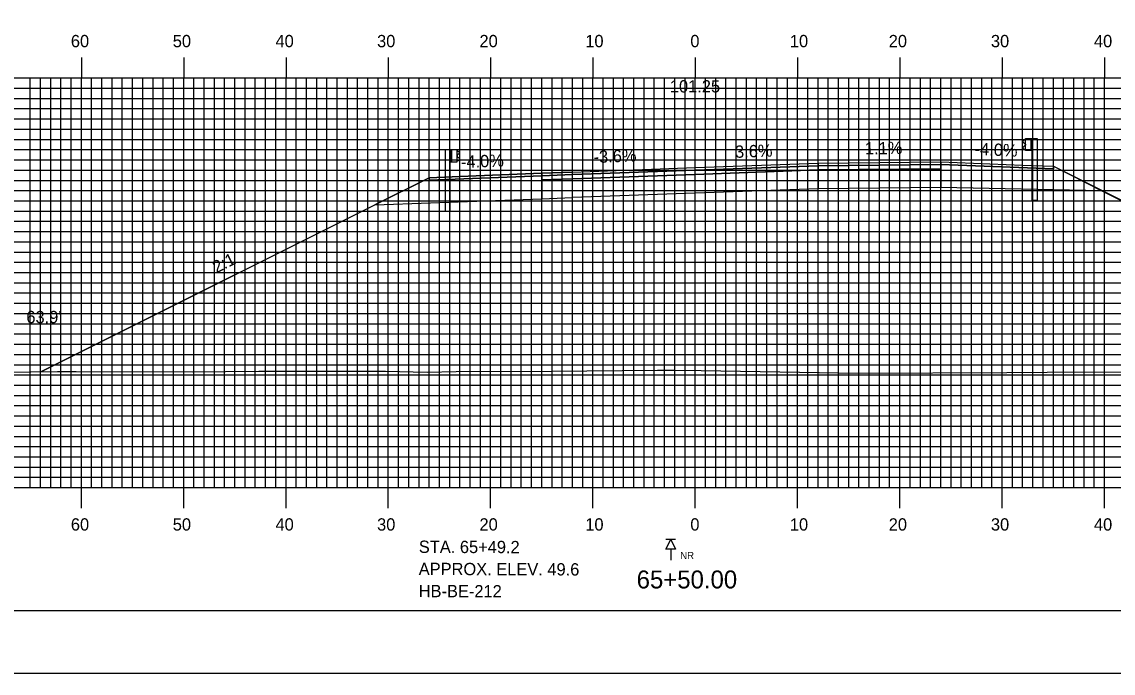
# Model space of a CAD drawing. Extents: x 1759036 to 1759380, y 442591 to 442811.
# Drawn here: x 1759136.3 to 1759243, y 442590.5 to 442654.1 of the extents above; entities that cross this region are included whole.
import ezdxf

# ---------------------------------------------------------------- set-up
doc = ezdxf.new("R2010")
doc.units = 0
for name, color, linetype in [('ANNOTATION', 7, 'Continuous'), ('BORDER', 7, 'Continuous'), ('BORING - NO REFUSAL', 7, 'Continuous'), ('D_Guardrail_Beam_Lt', 7, 'Continuous'), ('D_Guardrail_Beam_Rt', 7, 'Continuous'), ('D_Roadway_Centerline', 7, 'Continuous'), ('D_Roadway_Centerline_Text', 7, 'Continuous'), ('D_Roadway_Edge_Shoulder', 7, 'Continuous'), ('D_Roadway_Edge_TW', 7, 'Continuous'), ('D_Roadway_Pavement', 7, 'Continuous'), ('D_Roadway_SlopeLines', 7, 'Continuous'), ('D_Roadway_SubGrade', 7, 'Continuous'), ('D_Text_Standard', 7, 'Continuous'), ('H_V ANNOTATION', 7, 'Continuous'), ('MAJOR', 7, 'Continuous'), ('MINOR', 7, 'Continuous'), ('PLOT BOUNDARY', 7, 'Continuous'), ('S_Roadway_Centerline', 7, 'Continuous')]:
    doc.layers.add(name, color=color, linetype=linetype)

msp = doc.modelspace()

# ---------------------------------------------------------------- linework, layer by layer
at = {"layer": 'BORDER'}
msp.add_lwpolyline([(1759052.56, 442596.67), (1759372.56, 442596.67), (1759372.56, 442806.67), (1759052.56, 442806.67)], close=True, dxfattribs=at)
at = {"layer": 'BORING - NO REFUSAL'}
for p, q in [((1759200.24, 442603.61), (1759199.28, 442603.61)), ((1759199.76, 442602.65), (1759199.76, 442601.59))]:
    msp.add_line(p, q, dxfattribs=at)
msp.add_lwpolyline([(1759199.76, 442603.61), (1759200.24, 442602.65), (1759199.28, 442602.65)], close=True, dxfattribs=at)
at = {"layer": 'D_Guardrail_Beam_Lt'}
for p, q in [((1759177.72, 442641.64), (1759177.72, 442635.64)), ((1759178.19, 442641.64), (1759177.72, 442641.64)), ((1759178.88, 442641.64), (1759178.19, 442641.64)), ((1759178.19, 442641.64), (1759178.19, 442640.47)), ((1759178.25, 442641.64), (1759178.25, 442640.47)), ((1759178.35, 442641.64), (1759178.35, 442640.47)), ((1759178.88, 442640.47), (1759178.88, 442641.64)), ((1759178.88, 442641.55), (1759178.95, 442641.54)), ((1759178.88, 442641.09), (1759178.88, 442641.02)), ((1759179.11, 442641.29), (1759178.91, 442641.15)), ((1759178.91, 442640.96), (1759179.11, 442640.82)), ((1759178.97, 442641.53), (1759179.11, 442641.43)), ((1759178.19, 442640.47), (1759178.88, 442640.47)), ((1759178.21, 442635.64), (1759178.21, 442640.47)), ((1759178.95, 442640.57), (1759178.88, 442640.55)), ((1759179.11, 442640.68), (1759178.97, 442640.58)), ((1759178.21, 442635.64), (1759177.72, 442635.64))]:
    msp.add_line(p, q, dxfattribs=at)
for centre, major_axis, start_param, end_param in [((1759178.96, 442641.09), (-0.0789, 0), 5.323254, 6.283185), ((1759178.96, 442641.02), (-0.0789, 0), 6.283185, 7.243116), ((1759178.94, 442641.5), (0.0417, 0), 0.959931, 1.376053), ((1759179.06, 442641.36), (0.0877, 0), 5.323254, 7.243116), ((1759179.06, 442640.75), (0.0877, 0), 5.323254, 7.243116), ((1759178.94, 442640.61), (0.0417, 0), 4.907132, 5.323254)]:
    msp.add_ellipse(centre, major_axis=major_axis, ratio=0.995501, start_param=start_param, end_param=end_param, dxfattribs=at)
at = {"layer": 'D_Guardrail_Beam_Rt'}
for p, q in [((1759234.34, 442642.64), (1759234.2, 442642.54)), ((1759234.2, 442642.4), (1759234.39, 442642.26)), ((1759234.39, 442642.06), (1759234.2, 442641.92)), ((1759234.43, 442642.66), (1759234.36, 442642.65)), ((1759234.43, 442642.74), (1759235.12, 442642.74)), ((1759234.43, 442641.58), (1759234.43, 442642.74)), ((1759234.43, 442642.19), (1759234.43, 442642.12)), ((1759234.95, 442642.74), (1759234.95, 442641.58)), ((1759235.06, 442642.74), (1759235.06, 442641.58)), ((1759235.12, 442642.74), (1759235.59, 442642.74)), ((1759235.12, 442642.74), (1759235.12, 442641.58)), ((1759235.59, 442642.74), (1759235.59, 442636.74)), ((1759234.2, 442641.78), (1759234.34, 442641.68)), ((1759234.36, 442641.67), (1759234.43, 442641.66)), ((1759235.12, 442641.58), (1759234.43, 442641.58)), ((1759235.1, 442636.74), (1759235.1, 442641.58)), ((1759235.1, 442636.74), (1759235.59, 442636.74))]:
    msp.add_line(p, q, dxfattribs=at)
for centre, major_axis, start_param, end_param in [((1759234.25, 442642.47), (-0.0877, 0), 5.323254, 7.243116), ((1759234.25, 442641.85), (-0.0877, 0), 5.323254, 7.243116), ((1759234.37, 442642.6), (-0.0417, 0), 4.907132, 5.323254), ((1759234.35, 442642.19), (0.0789, 0), 0, 0.959931), ((1759234.35, 442642.12), (0.0789, 0), 5.323254, 6.283185), ((1759234.37, 442641.72), (-0.0417, 0), 0.959931, 1.376053)]:
    msp.add_ellipse(centre, major_axis=major_axis, ratio=0.995501, start_param=start_param, end_param=end_param, dxfattribs=at)
at = {"layer": 'D_Roadway_Centerline'}
msp.add_lwpolyline([(1759138.26, 442619.99), (1759170.85, 442636.29), (1759176.15, 442638.93), (1759179.15, 442639.05), (1759187.15, 442639.37), (1759190.16, 442639.48), (1759202.16, 442639.92), (1759214.16, 442640.35), (1759226.16, 442640.48), (1759234.16, 442640.16), (1759237.16, 442640.04), (1759241.91, 442637.66), (1759276.4, 442620.42)], dxfattribs=at)
at = {"layer": 'D_Roadway_Edge_Shoulder'}
for points in [[(1759226.16, 442640.48), (1759234.16, 442640.16), (1759234.16, 442640.16), (1759237.16, 442640.04), (1759237.16, 442639.79), (1759226.16, 442640.23)], [(1759187.15, 442639.37), (1759179.15, 442639.05), (1759179.15, 442639.05), (1759176.15, 442638.93), (1759176.15, 442638.68), (1759187.15, 442639.12)]]:
    msp.add_lwpolyline(points, close=True, dxfattribs=at)
at = {"layer": 'D_Roadway_Edge_TW'}
for points in [[(1759190.16, 442639.23), (1759190.16, 442639.48), (1759202.16, 442639.92), (1759214.16, 442640.35), (1759214.16, 442640.1), (1759202.16, 442639.67)], [(1759214.16, 442640.35), (1759226.16, 442640.48), (1759226.16, 442640.23), (1759214.16, 442640.1)], [(1759190.16, 442639.48), (1759187.15, 442639.37), (1759187.15, 442639.12), (1759190.16, 442639.23)]]:
    msp.add_lwpolyline(points, close=True, dxfattribs=at)
at = {"layer": 'D_Roadway_Pavement'}
for points in [[(1759190.16, 442638.82), (1759190.16, 442639.23), (1759202.16, 442639.67), (1759214.16, 442640.1), (1759214.16, 442639.68), (1759202.16, 442639.25)], [(1759214.16, 442640.1), (1759226.16, 442640.23), (1759226.16, 442639.81), (1759214.16, 442639.68)], [(1759190.16, 442639.23), (1759187.15, 442639.12), (1759187.15, 442638.71), (1759190.16, 442638.82)]]:
    msp.add_lwpolyline(points, close=True, dxfattribs=at)
for points in [[(1759226.16, 442640.23), (1759226.16, 442639.81)], [(1759226.16, 442640.23), (1759226.16, 442639.81)], [(1759226.16, 442640.23), (1759226.16, 442639.81)], [(1759226.16, 442640.23), (1759226.16, 442639.81)], [(1759226.16, 442640.23), (1759226.16, 442639.81)], [(1759187.15, 442639.12), (1759187.15, 442638.71)], [(1759187.15, 442639.12), (1759187.15, 442638.71)]]:
    msp.add_lwpolyline(points, dxfattribs=at)
at = {"layer": 'D_Roadway_SlopeLines'}
for points in [[(1759237.16, 442640.04), (1759276.4, 442620.42)], [(1759176.15, 442638.93), (1759138.26, 442619.99)]]:
    msp.add_lwpolyline(points, dxfattribs=at)
at = {"layer": 'D_Roadway_SubGrade'}
for points in [[(1759214.16, 442639.68), (1759226.16, 442639.81), (1759226.16, 442637.98), (1759214.16, 442637.85)], [(1759226.16, 442639.81), (1759226.16, 442640.23), (1759237.16, 442639.79), (1759237.16, 442640.04), (1759241.91, 442637.66), (1759226.16, 442637.98)], [(1759187.15, 442638.71), (1759187.15, 442639.12), (1759176.15, 442638.68), (1759176.15, 442638.93), (1759170.85, 442636.29), (1759187.15, 442636.87)], [(1759190.16, 442638.82), (1759187.15, 442638.71), (1759187.15, 442636.87), (1759190.16, 442636.98)], [(1759190.16, 442636.98), (1759190.16, 442638.82), (1759202.16, 442639.25), (1759214.16, 442639.68), (1759214.16, 442637.85), (1759202.16, 442637.42)]]:
    msp.add_lwpolyline(points, close=True, dxfattribs=at)
at = {"layer": 'MAJOR'}
for p, q in [((1759142.16, 442650.67), (1759142.16, 442648.67)), ((1759152.16, 442650.67), (1759152.16, 442648.67)), ((1759162.16, 442650.67), (1759162.16, 442648.67)), ((1759172.16, 442650.67), (1759172.16, 442648.67)), ((1759182.16, 442650.67), (1759182.16, 442648.67)), ((1759192.16, 442650.67), (1759192.16, 442648.67)), ((1759202.16, 442650.67), (1759202.16, 442648.67)), ((1759212.16, 442650.67), (1759212.16, 442648.67)), ((1759222.16, 442650.67), (1759222.16, 442648.67)), ((1759232.16, 442650.67), (1759232.16, 442648.67)), ((1759242.16, 442650.67), (1759242.16, 442648.67)), ((1759062.16, 442648.67), (1759342.16, 442648.67)), ((1759062.16, 442648.67), (1759342.16, 442648.67)), ((1759142.16, 442608.67), (1759142.16, 442648.67)), ((1759152.16, 442608.67), (1759152.16, 442648.67)), ((1759162.16, 442608.67), (1759162.16, 442648.67)), ((1759172.16, 442608.67), (1759172.16, 442648.67)), ((1759182.16, 442608.67), (1759182.16, 442648.67)), ((1759192.16, 442608.67), (1759192.16, 442648.67)), ((1759202.16, 442608.67), (1759202.16, 442648.67)), ((1759212.16, 442608.67), (1759212.16, 442648.67)), ((1759222.16, 442608.67), (1759222.16, 442648.67)), ((1759232.16, 442608.67), (1759232.16, 442648.67)), ((1759242.16, 442608.67), (1759242.16, 442648.67)), ((1759062.16, 442643.67), (1759342.16, 442643.67)), ((1759062.16, 442638.67), (1759342.16, 442638.67)), ((1759062.16, 442633.67), (1759342.16, 442633.67)), ((1759062.16, 442628.67), (1759342.16, 442628.67)), ((1759062.16, 442623.67), (1759342.16, 442623.67)), ((1759062.16, 442618.67), (1759342.16, 442618.67)), ((1759062.16, 442613.67), (1759342.16, 442613.67)), ((1759062.16, 442608.67), (1759342.16, 442608.67)), ((1759062.16, 442608.67), (1759342.16, 442608.67)), ((1759142.16, 442606.66), (1759142.16, 442608.67)), ((1759152.16, 442606.66), (1759152.16, 442608.67)), ((1759162.16, 442606.66), (1759162.16, 442608.67)), ((1759172.16, 442606.66), (1759172.16, 442608.67)), ((1759182.16, 442606.66), (1759182.16, 442608.67)), ((1759192.16, 442606.66), (1759192.16, 442608.67)), ((1759202.16, 442606.66), (1759202.16, 442608.67)), ((1759212.16, 442606.66), (1759212.16, 442608.67)), ((1759222.16, 442606.66), (1759222.16, 442608.67)), ((1759232.16, 442606.66), (1759232.16, 442608.67)), ((1759242.16, 442606.66), (1759242.16, 442608.67))]:
    msp.add_line(p, q, dxfattribs=at)
at = {"layer": 'MINOR'}
for p, q in [((1759137.16, 442608.67), (1759137.16, 442648.67)), ((1759138.16, 442608.67), (1759138.16, 442648.67)), ((1759139.16, 442608.67), (1759139.16, 442648.67)), ((1759140.16, 442608.67), (1759140.16, 442648.67)), ((1759141.16, 442608.67), (1759141.16, 442648.67)), ((1759143.16, 442608.67), (1759143.16, 442648.67)), ((1759144.16, 442608.67), (1759144.16, 442648.67)), ((1759145.16, 442608.67), (1759145.16, 442648.67)), ((1759146.16, 442608.67), (1759146.16, 442648.67)), ((1759147.16, 442608.67), (1759147.16, 442648.67)), ((1759148.16, 442608.67), (1759148.16, 442648.67)), ((1759149.16, 442608.67), (1759149.16, 442648.67)), ((1759150.16, 442608.67), (1759150.16, 442648.67)), ((1759151.16, 442608.67), (1759151.16, 442648.67)), ((1759153.16, 442608.67), (1759153.16, 442648.67)), ((1759154.16, 442608.67), (1759154.16, 442648.67)), ((1759155.16, 442608.67), (1759155.16, 442648.67)), ((1759156.16, 442608.67), (1759156.16, 442648.67)), ((1759157.16, 442608.67), (1759157.16, 442648.67)), ((1759158.16, 442608.67), (1759158.16, 442648.67)), ((1759159.16, 442608.67), (1759159.16, 442648.67)), ((1759160.16, 442608.67), (1759160.16, 442648.67)), ((1759161.16, 442608.67), (1759161.16, 442648.67)), ((1759163.16, 442608.67), (1759163.16, 442648.67)), ((1759164.16, 442608.67), (1759164.16, 442648.67)), ((1759165.16, 442608.67), (1759165.16, 442648.67)), ((1759166.16, 442608.67), (1759166.16, 442648.67)), ((1759167.16, 442608.67), (1759167.16, 442648.67)), ((1759168.16, 442608.67), (1759168.16, 442648.67)), ((1759169.16, 442608.67), (1759169.16, 442648.67)), ((1759170.16, 442608.67), (1759170.16, 442648.67)), ((1759171.16, 442608.67), (1759171.16, 442648.67)), ((1759173.16, 442608.67), (1759173.16, 442648.67)), ((1759174.16, 442608.67), (1759174.16, 442648.67)), ((1759175.16, 442608.67), (1759175.16, 442648.67)), ((1759176.16, 442608.67), (1759176.16, 442648.67)), ((1759177.16, 442608.67), (1759177.16, 442648.67)), ((1759178.16, 442608.67), (1759178.16, 442648.67)), ((1759179.16, 442608.67), (1759179.16, 442648.67)), ((1759180.16, 442608.67), (1759180.16, 442648.67)), ((1759181.16, 442608.67), (1759181.16, 442648.67)), ((1759183.16, 442608.67), (1759183.16, 442648.67)), ((1759184.16, 442608.67), (1759184.16, 442648.67)), ((1759185.16, 442608.67), (1759185.16, 442648.67)), ((1759186.16, 442608.67), (1759186.16, 442648.67)), ((1759187.16, 442608.67), (1759187.16, 442648.67)), ((1759188.16, 442608.67), (1759188.16, 442648.67)), ((1759189.16, 442608.67), (1759189.16, 442648.67)), ((1759190.16, 442608.67), (1759190.16, 442648.67)), ((1759191.16, 442608.67), (1759191.16, 442648.67)), ((1759193.16, 442608.67), (1759193.16, 442648.67)), ((1759194.16, 442608.67), (1759194.16, 442648.67)), ((1759195.16, 442608.67), (1759195.16, 442648.67)), ((1759196.16, 442608.67), (1759196.16, 442648.67)), ((1759197.16, 442608.67), (1759197.16, 442648.67)), ((1759198.16, 442608.67), (1759198.16, 442648.67)), ((1759199.16, 442608.67), (1759199.16, 442648.67)), ((1759200.16, 442608.67), (1759200.16, 442648.67)), ((1759201.16, 442608.67), (1759201.16, 442648.67)), ((1759203.16, 442608.67), (1759203.16, 442648.67)), ((1759204.16, 442608.67), (1759204.16, 442648.67)), ((1759205.16, 442608.67), (1759205.16, 442648.67)), ((1759206.16, 442608.67), (1759206.16, 442648.67)), ((1759207.16, 442608.67), (1759207.16, 442648.67)), ((1759208.16, 442608.67), (1759208.16, 442648.67)), ((1759209.16, 442608.67), (1759209.16, 442648.67)), ((1759210.16, 442608.67), (1759210.16, 442648.67)), ((1759211.16, 442608.67), (1759211.16, 442648.67)), ((1759213.16, 442608.67), (1759213.16, 442648.67)), ((1759214.16, 442608.67), (1759214.16, 442648.67)), ((1759215.16, 442608.67), (1759215.16, 442648.67)), ((1759216.16, 442608.67), (1759216.16, 442648.67)), ((1759217.16, 442608.67), (1759217.16, 442648.67)), ((1759218.16, 442608.67), (1759218.16, 442648.67)), ((1759219.16, 442608.67), (1759219.16, 442648.67)), ((1759220.16, 442608.67), (1759220.16, 442648.67)), ((1759221.16, 442608.67), (1759221.16, 442648.67)), ((1759223.16, 442608.67), (1759223.16, 442648.67)), ((1759224.16, 442608.67), (1759224.16, 442648.67)), ((1759225.16, 442608.67), (1759225.16, 442648.67)), ((1759226.16, 442608.67), (1759226.16, 442648.67)), ((1759227.16, 442608.67), (1759227.16, 442648.67)), ((1759228.16, 442608.67), (1759228.16, 442648.67)), ((1759229.16, 442608.67), (1759229.16, 442648.67)), ((1759230.16, 442608.67), (1759230.16, 442648.67)), ((1759231.16, 442608.67), (1759231.16, 442648.67)), ((1759233.16, 442608.67), (1759233.16, 442648.67)), ((1759234.16, 442608.67), (1759234.16, 442648.67)), ((1759235.16, 442608.67), (1759235.16, 442648.67)), ((1759236.16, 442608.67), (1759236.16, 442648.67)), ((1759237.16, 442608.67), (1759237.16, 442648.67)), ((1759238.16, 442608.67), (1759238.16, 442648.67)), ((1759239.16, 442608.67), (1759239.16, 442648.67)), ((1759240.16, 442608.67), (1759240.16, 442648.67)), ((1759241.16, 442608.67), (1759241.16, 442648.67)), ((1759062.16, 442647.67), (1759342.16, 442647.67)), ((1759062.16, 442646.67), (1759342.16, 442646.67)), ((1759062.16, 442645.67), (1759342.16, 442645.67)), ((1759062.16, 442644.67), (1759342.16, 442644.67)), ((1759062.16, 442642.67), (1759342.16, 442642.67)), ((1759062.16, 442641.67), (1759342.16, 442641.67)), ((1759062.16, 442640.67), (1759342.16, 442640.67)), ((1759062.16, 442639.67), (1759342.16, 442639.67)), ((1759062.16, 442637.67), (1759342.16, 442637.67)), ((1759062.16, 442636.67), (1759342.16, 442636.67)), ((1759062.16, 442635.67), (1759342.16, 442635.67)), ((1759062.16, 442634.67), (1759342.16, 442634.67)), ((1759062.16, 442632.67), (1759342.16, 442632.67)), ((1759062.16, 442631.67), (1759342.16, 442631.67)), ((1759062.16, 442630.67), (1759342.16, 442630.67)), ((1759062.16, 442629.67), (1759342.16, 442629.67)), ((1759062.16, 442627.67), (1759342.16, 442627.67)), ((1759062.16, 442626.67), (1759342.16, 442626.67)), ((1759062.16, 442625.67), (1759342.16, 442625.67)), ((1759062.16, 442624.67), (1759342.16, 442624.67)), ((1759062.16, 442622.67), (1759342.16, 442622.67)), ((1759062.16, 442621.67), (1759342.16, 442621.67)), ((1759062.16, 442620.67), (1759342.16, 442620.67)), ((1759062.16, 442619.67), (1759342.16, 442619.67)), ((1759062.16, 442617.67), (1759342.16, 442617.67)), ((1759062.16, 442616.67), (1759342.16, 442616.67)), ((1759062.16, 442615.67), (1759342.16, 442615.67)), ((1759062.16, 442614.67), (1759342.16, 442614.67)), ((1759062.16, 442612.67), (1759342.16, 442612.67)), ((1759062.16, 442611.67), (1759342.16, 442611.67)), ((1759062.16, 442610.67), (1759342.16, 442610.67)), ((1759062.16, 442609.67), (1759342.16, 442609.67))]:
    msp.add_line(p, q, dxfattribs=at)
at = {"layer": 'PLOT BOUNDARY'}
msp.add_lwpolyline([(1759036.37, 442590.55), (1759376.37, 442590.55), (1759376.37, 442810.55), (1759036.37, 442810.55)], close=True, dxfattribs=at)
at = {"layer": 'S_Roadway_Centerline'}
msp.add_lwpolyline([(1759121.52, 442619.88), (1759137.23, 442619.98), (1759139.81, 442620), (1759140.5, 442620.01), (1759141.66, 442620), (1759152.98, 442619.98), (1759159.49, 442620.02), (1759171.89, 442620.03), (1759175.97, 442619.95), (1759178.78, 442619.99), (1759188.11, 442620.03), (1759198.48, 442620.14), (1759200.11, 442620.14), (1759202.74, 442620.09), (1759218.12, 442619.83), (1759232.63, 442619.9), (1759236.55, 442619.93), (1759247.16, 442619.97)], dxfattribs=at)

# ---------------------------------------------------------------- texts
at = {"layer": 'ANNOTATION'}
for s, rotation, p in [('3.6%', 2.0618, (1759206.07, 442640.86)), ('1.1%', 0.6338, (1759218.75, 442641.2)), ('-4.0%', 357.7094, (1759229.45, 442641.15)), ('-4.0%', 2.2906, (1759179.28, 442639.86)), ('-3.6%', 2.0618, (1759192.24, 442640.36)), ('2:1', 26.5651, (1759155.35, 442629.57))]:
    msp.add_text(s, height=1.2, rotation=rotation, dxfattribs=at).set_placement(p)
at = {"layer": 'BORING - NO REFUSAL'}
for s, p in [('STA. 65+49.2', (1759175.14, 442602.29)), ('APPROX. ELEV. 49.6', (1759175.13, 442600.13)), ('HB-BE-212', (1759175.13, 442597.97))]:
    msp.add_text(s, height=1.2, rotation=359.8142, dxfattribs=at).set_placement(p)
msp.add_text('NR', height=0.7, dxfattribs=at).set_placement((1759200.69, 442601.69))
at = {"layer": 'D_Roadway_Centerline'}
for s, p in [('C', (1759202.16, 442639.92)), ('L', (1759202.16, 442639.91))]:
    msp.add_text(s, height=0.0146, dxfattribs=at).set_placement(p)
at = {"layer": 'D_Roadway_Centerline_Text'}
msp.add_text('101.25', height=1.2, dxfattribs=at).set_placement((1759199.68, 442647.25))
at = {"layer": 'D_Text_Standard'}
msp.add_text("63.9'", height=1.2, dxfattribs=at).set_placement((1759136.78, 442624.72))
at = {"layer": 'H_V ANNOTATION'}
for s, height, p in [('60', 1.2, (1759141.13, 442651.67)), ('50', 1.2, (1759151.09, 442651.67)), ('40', 1.2, (1759161.13, 442651.67)), ('30', 1.2, (1759171.06, 442651.67)), ('20', 1.2, (1759181.07, 442651.67)), ('10', 1.2, (1759191.41, 442651.67)), ('0', 1.2, (1759201.68, 442651.67)), ('10', 1.2, (1759211.41, 442651.67)), ('20', 1.2, (1759221.07, 442651.67)), ('30', 1.2, (1759231.06, 442651.67)), ('40', 1.2, (1759241.13, 442651.67)), ('60', 1.2, (1759141.13, 442604.47)), ('50', 1.2, (1759151.09, 442604.47)), ('40', 1.2, (1759161.13, 442604.47)), ('30', 1.2, (1759171.06, 442604.47)), ('20', 1.2, (1759181.07, 442604.47)), ('10', 1.2, (1759191.41, 442604.47)), ('0', 1.2, (1759201.68, 442604.47)), ('10', 1.2, (1759211.41, 442604.47)), ('20', 1.2, (1759221.07, 442604.47)), ('30', 1.2, (1759231.06, 442604.47)), ('40', 1.2, (1759241.13, 442604.47)), ('65+50.00', 1.75, (1759196.43, 442598.82))]:
    msp.add_text(s, height=height, dxfattribs=at).set_placement(p)

doc.saveas('drawing.dxf')
